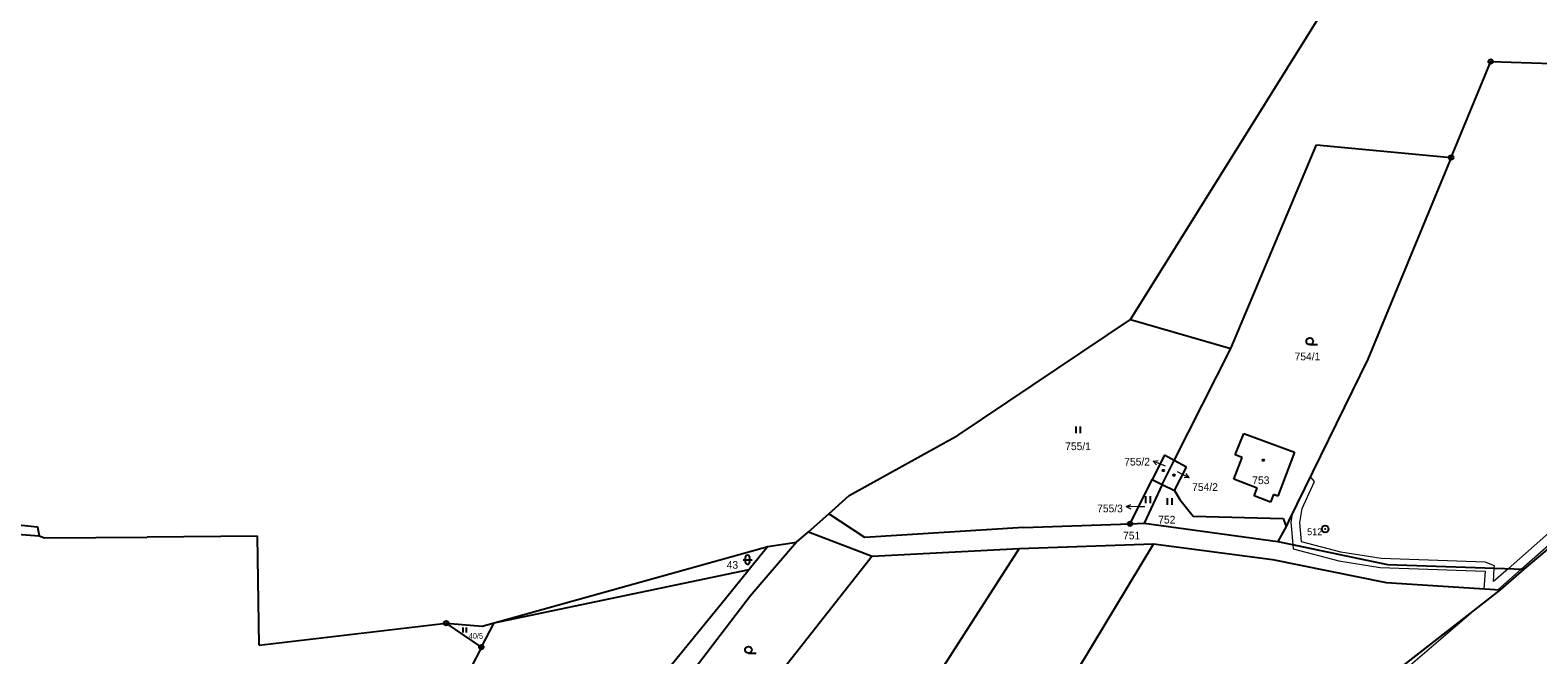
# Model space of a CAD drawing. Extents: x -727701 to -724405, y -960481 to -957284.
# Drawn here: x -726527.9 to -726194, y -958076.9 to -957938.6 of the extents above; entities that cross this region are included whole.
import ezdxf
from ezdxf.enums import TextEntityAlignment as Align

# ---------------------------------------------------------------- set-up
doc = ezdxf.new("R2010")
doc.units = 0
doc.header["$LTSCALE"] = 0.68
for name, color, linetype, lineweight in [('1', 7, 'Continuous', 25), ('13', 7, 'Continuous', 13), ('3', 7, 'Continuous', 25), ('5', 7, 'Continuous', 25), ('7', 7, 'Continuous', 13), ('8', 7, 'Continuous', 25)]:
    doc.layers.add(name, color=color, linetype=linetype, lineweight=lineweight)
doc.layers.add('2', color=7, linetype='Continuous')

msp = doc.modelspace()

# ---------------------------------------------------------------- linework, layer by layer
at = {"layer": '1'}
for p, q in [((-726213.18, -957966.81), (-726204.42, -957945.58)), ((-726204.42, -957945.58), (-726112.08, -957948.36)), ((-726262, -958009.1), (-726243, -957964)), ((-726243, -957964), (-726217.14, -957966.46)), ((-726213.18, -957966.81), (-726231.67, -958011.43)), ((-726217.14, -957966.46), (-726213.18, -957966.81)), ((-726322.38, -958028.24), (-726284.2, -958002.7)), ((-726284.2, -958002.7), (-726262, -958009.1)), ((-726274.5, -958033.85), (-726262, -958009.1)), ((-726231.67, -958011.43), (-726249.14, -958047.17)), ((-726346.49, -958041.59), (-726322.38, -958028.24)), ((-726261.02, -958032.65), (-726259.1, -958027.93)), ((-726259.1, -958027.93), (-726247.84, -958032.05)), ((-726162.41, -958028.69), (-726197.08, -958057.94)), ((-726276.66, -958032.71), (-726279.36, -958038.08)), ((-726277.15, -958039.2), (-726274.5, -958033.85)), ((-726274.5, -958033.85), (-726276.66, -958032.71)), ((-726271.76, -958035.33), (-726274.5, -958033.85)), ((-726261.33, -958037.98), (-726259.5, -958033.23)), ((-726259.5, -958033.23), (-726261.02, -958032.65)), ((-726247.84, -958032.05), (-726251.57, -958041.74)), ((-726274.47, -958040.54), (-726271.76, -958035.33)), ((-726284.29, -958047.88), (-726279.36, -958038.08)), ((-726277.15, -958039.2), (-726281.16, -958047.77)), ((-726279.36, -958038.08), (-726277.15, -958039.2)), ((-726277.15, -958039.2), (-726274.47, -958040.54)), ((-726274.47, -958040.54), (-726273.24, -958042.5)), ((-726256.13, -958039.98), (-726261.33, -958037.98)), ((-726256.8, -958041.71), (-726256.13, -958039.98)), ((-726351.01, -958045.65), (-726346.49, -958041.59)), ((-726273.24, -958042.5), (-726270.31, -958046.2)), ((-726253.2, -958043.1), (-726256.8, -958041.71)), ((-726252.54, -958041.37), (-726253.2, -958043.1)), ((-726251.57, -958041.74), (-726252.54, -958041.37)), ((-726355.49, -958049.67), (-726351.01, -958045.65)), ((-726343.02, -958050.91), (-726351.01, -958045.65)), ((-726270.31, -958046.2), (-726250.38, -958046.72)), ((-726250.38, -958046.72), (-726249.7, -958048.45)), ((-726249.14, -958047.17), (-726249.7, -958048.45)), ((-726533.66, -958049.94), (-726525.88, -958050.52)), ((-726524.67, -958051.03), (-726501.97, -958050.85)), ((-726477.51, -958050.65), (-726501.97, -958050.85)), ((-726477.17, -958074.76), (-726477.51, -958050.65)), ((-726358.18, -958051.92), (-726355.49, -958049.67)), ((-726355.49, -958049.67), (-726341.41, -958055.03)), ((-726307.9, -958048.7), (-726343.02, -958050.91)), ((-726307.9, -958048.7), (-726284.29, -958047.88)), ((-726284.29, -958047.88), (-726281.16, -958047.77)), ((-726281.16, -958047.77), (-726251.53, -958051.82)), ((-726249.7, -958048.45), (-726251.53, -958051.82)), ((-726425.12, -958069.8), (-726364.5, -958052.9)), ((-726364.5, -958052.9), (-726368.62, -958057.98)), ((-726358.18, -958051.92), (-726368.44, -958063.92)), ((-726364.5, -958052.9), (-726358.18, -958051.92)), ((-726341.41, -958055.03), (-726308.84, -958053.35)), ((-726308.84, -958053.35), (-726336.78, -958096.77)), ((-726308.84, -958053.35), (-726279.07, -958052.32)), ((-726279.07, -958052.32), (-726304.61, -958094.57)), ((-726279.07, -958052.32), (-726252.72, -958055.82)), ((-726251.53, -958051.82), (-726227.26, -958056.93)), ((-726341.41, -958055.03), (-726380.73, -958104.97)), ((-726252.72, -958055.82), (-726227.56, -958060.85)), ((-726227.26, -958056.93), (-726197.08, -958057.94)), ((-726425.12, -958069.8), (-726368.62, -958057.98)), ((-726368.62, -958057.98), (-726373.89, -958064.49)), ((-726227.56, -958060.85), (-726202.34, -958062.52)), ((-726197.08, -958057.94), (-726202.34, -958062.52)), ((-726368.44, -958063.92), (-726392.44, -958095.31)), ((-726202.34, -958062.52), (-726247.68, -958097.8)), ((-726373.89, -958064.49), (-726421.22, -958122.51)), ((-726477.17, -958074.76), (-726435.73, -958069.87)), ((-726427.95, -958075.18), (-726435.73, -958069.87)), ((-726435.73, -958069.87), (-726427.77, -958070.54)), ((-726427.95, -958075.18), (-726425.12, -958069.8)), ((-726427.77, -958070.54), (-726425.12, -958069.8)), ((-726427.95, -958075.18), (-726438.54, -958095.75))]:
    msp.add_line(p, q, dxfattribs=at)
for points in [[(-726284.2, -958002.7), (-726224.35, -957906.7), (-726193.01, -957816.84), (-726179.65, -957779.52), (-726172.26, -957763.42), (-726164, -957746.05), (-726156.41, -957730.56), (-726144.61, -957705.25), (-726133.8, -957684.95), (-726118.08, -957655.59), (-726102.79, -957628.23), (-726086.08, -957597.26), (-726074.13, -957573.46), (-726060.5, -957543.57), (-726049.09, -957519.01)], [(-726539.1, -958047.26), (-726526.27, -958048.56), (-726525.88, -958050.52), (-726524.67, -958051.03)]]:
    msp.add_lwpolyline(points, dxfattribs=at)
at = {"layer": '13'}
for points in [[(-726200.58, -958057.82), (-726197.66, -958057.92), (-726179.4, -958041.82), (-726158.11, -958024.15), (-726154.82, -958019.82), (-726155.57, -958019.44), (-726180.7, -958040.3)], [(-726244.38, -958037.43), (-726248.39, -958045.64), (-726248.71, -958047.54), (-726248.28, -958052.5), (-726227.26, -958056.93), (-726203.64, -958057.72), (-726203.6, -958057.17), (-726205.63, -958056.37), (-726228.7, -958055.55), (-726237.65, -958054.14), (-726246.33, -958051.88), (-726246.7, -958047.62), (-726246.17, -958044.5), (-726243.48, -958038.55)], [(-726248.2, -958053.46), (-726238.06, -958056.1), (-726228.89, -958057.55), (-726205.68, -958058.37), (-726205.94, -958062.28), (-726202.84, -958062.49), (-726197.66, -958057.92), (-726200.58, -958057.82), (-726203.83, -958060.69), (-726203.64, -958057.72), (-726227.26, -958056.93), (-726248.28, -958052.5)], [(-726207.74, -958066.72), (-726240.63, -958092.31), (-726289.25, -958134.25), (-726314.78, -958141.24), (-726320.34, -958144.83), (-726288.29, -958136.06), (-726230.48, -958086.2), (-726206.45, -958101.82), (-726205.07, -958100.33), (-726228.9, -958084.85)]]:
    msp.add_lwpolyline(points, close=True, dxfattribs=at)
at = {"layer": '3'}
for p, q in [((-726244.503, -958008.24), (-726242.753, -958008.24)), ((-726296.231, -958027.82), (-726296.231, -958026.32)), ((-726295.23, -958027.82), (-726295.23, -958026.32)), ((-726280.761, -958043.29), (-726280.761, -958041.79)), ((-726279.76, -958043.29), (-726279.76, -958041.79)), ((-726275.981, -958043.69), (-726275.981, -958042.19)), ((-726274.98, -958043.69), (-726274.98, -958042.19)), ((-726370.001, -958055.831), (-726367.999, -958055.831)), ((-726369.501, -958055.331), (-726369.501, -958056.332)), ((-726368.499, -958056.332), (-726368.499, -958055.331)), ((-726431.948, -958071.94), (-726431.948, -958070.86)), ((-726431.227, -958071.94), (-726431.227, -958070.86)), ((-726368.813, -958076.53), (-726367.063, -958076.53))]:
    msp.add_line(p, q, dxfattribs=at)
for centre in [(-726244.5029, -958007.4898), (-726368.8129, -958075.7798)]:
    msp.add_circle(centre, 0.75, dxfattribs=at)
for centre, start, end in [((-726369, -958055.3309), 0, 180), ((-726369, -958056.3309), 180, 359.98789)]:
    msp.add_arc(centre, 0.5, start, end, dxfattribs=at)
at = {"layer": '5'}
for centre in [(-726254.7768, -958033.7992), (-726276.9368, -958036.0892), (-726274.5668, -958037.1292)]:
    msp.add_circle(centre, 0.175, dxfattribs=at)
at = {"layer": '7'}
for p, q in [((-726279.192, -958033.996), (-726278.452, -958034.835)), ((-726271.186, -958037.682), (-726271.851, -958036.782)), ((-726285.141, -958044.088), (-726284.148, -958044.606))]:
    msp.add_line(p, q, dxfattribs=at)
for points in [[(-726276.41, -958035.12), (-726279.192, -958033.996), (-726278.076, -958033.907)], [(-726273.86, -958036.32), (-726271.186, -958037.682), (-726272.306, -958037.674)], [(-726281.03, -958044.17), (-726282.14, -958044.14), (-726285.141, -958044.088), (-726284.13, -958043.604)]]:
    msp.add_lwpolyline(points, dxfattribs=at)
at = {"layer": '8'}
for centre, radius in [((-726204.42, -957945.5799), 0.5), ((-726204.42, -957945.5799), 0.0303), ((-726213.18, -957966.8099), 0.5), ((-726213.18, -957966.8099), 0.0303), ((-726284.29, -958047.8799), 0.5), ((-726284.29, -958047.8799), 0.0303), ((-726241.08, -958049.0398), 0.75), ((-726241.08, -958049.0398), 0.03), ((-726435.73, -958069.8699), 0.5), ((-726435.73, -958069.8699), 0.0303), ((-726427.95, -958075.1799), 0.5), ((-726427.95, -958075.1799), 0.0303)]:
    msp.add_circle(centre, radius, dxfattribs=at)

# ---------------------------------------------------------------- texts
at = {"layer": '2'}
for s, height, p in [('754/1', 1.7, (-726245, -958011.705)), ('755/1', 1.7, (-726295.81, -958031.575)), ('40/5', 1.224, (-726429.16, -958073.316))]:
    msp.add_text(s, height=height, dxfattribs=at).set_placement(p, align=Align.CENTER)
for s, p in [('755/2', (-726279.88, -958034.992)), ('755/3', (-726285.89, -958045.342))]:
    msp.add_text(s, height=1.7, dxfattribs=at).set_placement(p, align=Align.RIGHT)
for s, p in [('753', (-726257.22, -958039.095)), ('754/2', (-726270.53, -958040.605)), ('752', (-726278.05, -958047.825)), ('751', (-726285.83, -958051.335)), ('43', (-726373.61, -958057.835))]:
    msp.add_text(s, height=1.7, dxfattribs=at).set_placement(p)
at = {"layer": '8'}
msp.add_text('512', height=1.5, dxfattribs=at).set_placement((-726245.08, -958050.405))

doc.saveas('drawing.dxf')
